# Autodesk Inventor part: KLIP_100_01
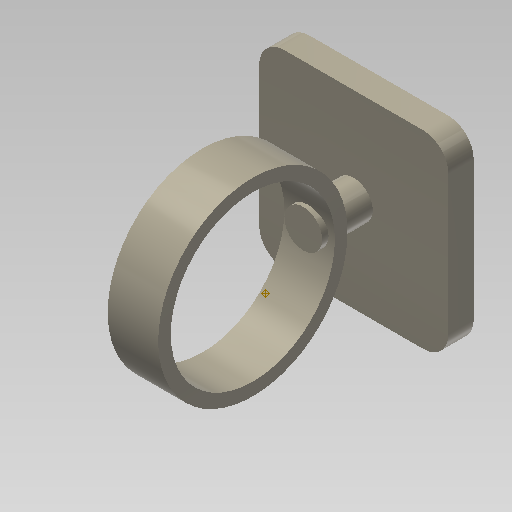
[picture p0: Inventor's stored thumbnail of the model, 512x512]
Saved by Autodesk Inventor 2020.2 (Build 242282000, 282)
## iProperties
Created: 2014-09
Part Number: KLIP_100_01
Material: Tworzywo sztuczne ABS
Document SubType Name: Modeling
Designer: F.Stasiak
Density: 1.06 g/cm^3
Appearance: Jasnobeżowa
Catalog Web Link: www.expertbooks.pl
Manager: www.cadconsulting.pl
Company: Fabian Stasiak CAD Consulting
Author: F.Stasiak
Subject: Zbiór ćwiczeń. Autodesk Inventor 2020. Kurs Professional
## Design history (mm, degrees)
sketch "Szkic1"
  geometry: L1 (-7.5, 7.5)-(7.5, 7.5); L2 (7.5, 7.5)-(7.5, -7.5); L3 (7.5, -7.5)-(-7.5, -7.5); L4 (-7.5, -7.5)-(-7.5, 7.5); L5 (-7.5, 7.5)-(7.5, -7.5); L6 (7.5, 7.5)-(-7.5, -7.5); 1 further point
  constraints: 12 end point, 2 midpoint, 2 parallel, 1 horizontal, 1 perpendicular
  dimensions: "d0" = 15 distance of L2.end L3.end; "d1" = 15 distance of L1.end L2.end
extrude "Wyciągnięcie proste1" new body sketch "Szkic1" distance "d2" = 2; taper "d3" = 0 deg
sketch "Szkic2"
  geometry: L1 (-1.5, 1.5)-(1.5, 1.5); L2 (1.5, 1.5)-(1.5, -1.5); L3 (1.5, -1.5)-(-1.5, -1.5); L4 (-1.5, -1.5)-(-1.5, 1.5); L5 (-1.5, 1.5)-(1.5, -1.5); L6 (1.5, 1.5)-(-1.5, -1.5); 1 further point
  constraints: 12 end point, 2 midpoint, 2 parallel, 1 horizontal, 1 perpendicular
  dimensions: "d4" = 3 distance of L2.end L3.end; "d5" = 3 distance of L1.end L2.end
extrude "Wyciągnięcie proste2" join sketch "Szkic2" distance "d6" = 4; taper "d7" = 0 deg
sketch "Szkic3"
  geometry: L1 (-7.5, 2)-(7.5, 2) reference; C1 r 7.5 at (0, 12); C2 r 6.5 at (0, 12); 1 further point
  constraints: 2 centre point, 1 coincident
  dimensions: "d20" = 10 distance from line of L1 C1.centre; "d21" = 1 radial gap between concentric circles of C1 C2; "d24" = 15 diameter of C1
fillet "Zaokrąglenie1" dims "d16" = 2
fillet "Zaokrąglenie2" dims "d17" = 1.5
node "Oś konstrukcyjna1"
node "Płaszczyzna konstrukcyjna1"
node "Płaszczyzna konstrukcyjna2"
node "Punkt konstrukcyjny1"
node "Punkt konstrukcyjny2"
extrude "Wyciągnięcie proste5" join sketch "Szkic3" stored distance "d22" = 4; taper "d23" = 0 deg
node "Bryła1"
other parameters: "d18" = 3, "d19" = -3
